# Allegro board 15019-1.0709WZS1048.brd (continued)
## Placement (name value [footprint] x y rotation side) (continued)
R1672  10KR2J-3-GP  [R402H16]  73.52 51.59 270 top
R1673  2K2R2J-2-GP  [R402H16]  84.36 143.51 0 top
R1674  10KR2J-3-GP  [R402H16]  83.35 143.51 0 top
R1675  2K2R2J-2-GP  [R402H16]  56.68 165.74 270 top
R1676  2K2R2J-2-GP  [R402H16]  62.26 156.72 270 top
R1677  47KR2J-2-GP  [R402H16]  52.36 157.86 90 top
R1678  33R2J-2-GP  [R402H16]  56.29 148.84 90 top
R1679  10KR2J-3-GP  [R402H16]  56.8 156.59 270 top
R1683  10KR2J-3-GP  [R402H16]  75.85 49.2 180 top
R1684  10KR2J-3-GP  [R402H16]  70.26 143.38 180 top
R1685  10KR2J-3-GP  [R402H16]  71.28 143.38 0 top
R1686  10R2F-L-GP  [R402H14]  67.98 143.38 0 top
R1687  10KR2J-3-GP  [R402H16]  83.47 138.18 270 top
R1688  10KR2J-3-GP  [R402H16]  83.47 139.19 90 top
R1690  15KR2F-GP  [R402H16]  56.8 160.66 90 top
R1691  15KR2F-GP  [R402H16]  62.26 158.75 90 top
R1696  39D2R2F-L-GP  [R402H16]  94.14 162.69 270 bottom
R1697  0R0402-PAD-2-GP  [0R0402-PAD-1]  86.01 186.56 0 top
R1698  0R0402-PAD-2-GP  [0R0402-PAD-1]  96.17 221.87 0 top
R1699  4K7R2J-2-GP  [R402H16]  115.35 59.56 270 top
R1700  10KR2J-3-GP  [R402H16]  117.25 59.56 90 top
R1701  10KR2J-3-GP  [R402H16]  91.35 222 0 top
R1702  10KR2J-3-GP  [R402H16]  100.11 214.38 90 top
R1703  10KR2J-3-GP  [R402H16]  100.11 215.65 90 top
R1704  1KR2J-1-GP  [R402H16]  100.11 209.3 90 top
R1705  10KR2J-3-GP  [R402H16]  100.11 216.92 90 top
R1707  10KR2J-3-GP  [R402H16]  122.08 204.98 90 top
R1708  0R5J-5-GP  [R805H24]  127.8 205.99 180 bottom
R1709  0R0402-PAD-2-GP  [0R0402-PAD-1]  104.17 217.17 270 top
R1710  0R2J-2-GP  [R402H16]  122.08 216.41 270 top
R1711  0R0402-PAD-2-GP  [0R0402-PAD-1]  104.17 213.11 270 top
R1712  0R0402-PAD-2-GP  [0R0402-PAD-1]  104.17 214.12 270 top
R1713  0R0402-PAD-2-GP  [0R0402-PAD-1]  104.17 211.07 270 top
R1714  0R0402-PAD-2-GP  [0R0402-PAD-1]  104.17 212.09 270 top
R1716  10KR2J-3-GP  [R402H16]  130 217.96 90 top
R1717  0R2J-2-GP  [R402H16]  122.08 221.49 270 top
R1718  0R0402-PAD-2-GP  [0R0402-PAD-1]  122.08 223.52 270 top
R1719  0R0402-PAD-2-GP  [0R0402-PAD-1]  104.17 220.22 270 top
R1720  1KR2J-1-GP  [R402H16]  86.01 190.63 180 top
R1721  1KR2F-3-GP  [R402H16]  161.2 111 90 top
R1724  10KR2J-3-GP  [R402H16]  56.8 168.78 270 top
R1725  10KR2J-3-GP  [R402H16]  105.57 29.59 180 top
R1727  15KR2F-GP  [R402H16]  174.15 125.73 0 top
R1728  10KR2J-3-GP  [R402H16]  173.13 125.73 180 top
R1729  1KR2J-1-GP  [R402H16]  169.71 126.36 90 top
R1730  1KR2J-1-GP  [R402H16]  31.53 35.05 270 top
R1731  10KR2J-3-GP  [R402H16]  31.53 32 270 top
R1732  1KR2J-1-GP  [R402H16]  31.53 29.97 270 top
R1733  10KR2J-3-GP  [R402H16]  31.53 30.99 270 top
R1734  10KR2J-3-GP  [R402H16]  31.53 34.04 270 top
R1735  10R2F-L-GP  [R402H14]  65.44 146.18 270 top
R1736  10KR2J-3-GP  [R402H16]  34.45 135.76 0 top
R1737  10KR2J-3-GP  [R402H16]  35.72 119.89 180 top
R1738  10KR2J-3-GP  [R402H16]  36.99 135.76 0 top
R1739  0R0402-PAD-2-GP  [0R0402-PAD-1]  33.18 119.89 0 top
R1740  0R0402-PAD-2-GP  [0R0402-PAD-1]  35.72 135.76 0 top
R1741  0R0402-PAD-2-GP  [0R0402-PAD-1]  35.34 117.6 90 top
R1743  33R2J-2-GP  [R402H16]  100.11 213.11 90 top
R1744  0R0402-PAD-2-GP  [0R0402-PAD-1]  89.44 213.11 270 top
R1745  0R0402-PAD-2-GP  [0R0402-PAD-1]  89.44 214.38 270 top
R1746  0R0402-PAD-2-GP  [0R0402-PAD-1]  89.44 216.92 270 top
R1747  0R0402-PAD-2-GP  [0R0402-PAD-1]  89.44 218.19 270 top
R1748  0R0402-PAD-2-GP  [0R0402-PAD-1]  89.44 219.46 270 top
R1749  10KR2J-3-GP  [R402H16]  87.66 143.38 0 top
R1751  75R3F-GP  [R603H22]  28.35 18.54 270 bottom
R1752  4K7R2J-2-GP  [R402H16]  30.64 16.13 270 top
R1753  10KR2J-3-GP  [R402H16]  25.18 28.7 90 bottom
R1754  10KR2J-3-GP  [R402H16]  28.99 29.72 270 bottom
R1755  33R2J-2-GP  [R402H16]  32.04 24.26 0 top
R1756  33R2J-2-GP  [R402H16]  27.85 26.67 0 bottom
R1757  10KR2J-3-GP  [R402H16]  36.61 28.57 0 top
R1758  4K7R2J-2-GP  [R402H16]  33.05 26.16 0 top
R1759  10KR2J-3-GP  [R402H16]  29.88 25.15 90 bottom
R1760  10KR2F-2-GP  [R402H16]  26.83 26.67 180 bottom
R1761  0R2J-2-GP  [R402H16]  28.48 17.4 90 bottom
R1762  0R0402-PAD-2-GP  [0R0402-PAD-1]  106.46 8.51 90 top
R1763  0R2J-2-GP  [R402H16]  16.92 159.13 180 bottom
R1764  0R2J-2-GP  [R402H16]  17.94 159.13 0 bottom
R1767  1K5R3-GP  [R603H22]  93.89 7.24 0 top
R1774  0R2J-2-GP  [R402H16]  62.64 148.89 90 top
R1776  47KR2F-GP  [R402H16]  60.23 143.51 270 top
R1777  470KR2F-GP  [R402H16]  91.6 19.56 180 top
R1778  470KR2F-GP  [R402H16]  35.21 141.22 90 top
R1779  1MR2J-1-GP  [R402H16]  91.6 21.46 180 top
R1780  100KR2J-1-GP  [R402H16]  90.58 19.56 180 top
R1781  100KR2J-1-GP  [R402H16]  90.08 21.08 270 top
R1782  4K7R2J-2-GP  [R402H16]  90.08 22.1 90 top
R1783  10KR2J-3-GP  [R402H16]  94.78 23.62 270 top
R1784  0R3J-0-U-GP  [R603H22]  161.73 188.77 90 bottom
R1785  10KR2J-3-GP  [R402H16]  29.62 14.1 0 top
R1808  10KR2F-2-GP  [R402H16]  142.65 72.39 180 top
R1809  10KR2F-2-GP  [R402H16]  141.38 72.39 180 top
R1810  0R2J-2-GP  [R402H16]  142.02 73.91 90 top
R1813  20KR2F-L-GP  [R402H16]  56.8 169.8 270 top
R1816  2KR2F-3-GP  [R402H16]  31.78 8 0 bottom
R1817  15KR2F-GP  [R402H16]  31.4 5.59 90 top
R1819  10KR2J-3-GP  [R402H16]  40.29 9.78 0 top
R1823  10KR2F-2-GP  [R402H16]  131.73 46.86 90 top
R1824  10KR2F-2-GP  [R402H16]  131.68 49.15 90 top
R1825  10KR2J-3-GP  [R402H16]  143.8 64.26 180 top
R1826  10KR2J-3-GP  [R402H16]  162.09 57.66 90 top
R1829  10KR2J-3-GP  [R402H16]  155.1 41.15 0 top
R1830  10KR2F-2-GP  [R402H16]  139.73 45.59 0 top
R1831  4K7R2J-2-GP  [R402H16]  152.69 43.94 0 bottom
R1832  10KR2F-2-GP  [R402H16]  138.84 41.4 90 top
R1833  17K8R2F-GP  [R402H16]  135.92 45.09 0 top
R1834  10KR2F-2-GP  [R402H16]  147.35 56.77 180 bottom
R1835  10KR2F-2-GP  [R402H16]  139.1 48.13 90 bottom
R1837  1KR2J-1-GP  [R402H16]  138.72 50.55 0 top
R1838  17K8R2F-GP  [R402H16]  139.1 47.12 270 top
R1840  10KR2J-3-GP  [R402H16]  144.81 64.26 180 top
R1841  10KR2F-2-GP  [R402H16]  139.1 48.13 270 top
R1842  0R0402-PAD-2-GP  [0R0402-PAD-1]  156.12 47.75 180 bottom
R1843  2K2R2J-2-GP  [R402H16]  146.85 62.48 270 bottom
R1844  4K7R2J-2-GP  [R402H16]  133.38 50.8 180 top
R1845  10KR2J-3-GP  [R402H16]  152.69 56.01 180 bottom
R1846  1K5R3-GP  [R603H22]  60.18 34.74 0 bottom
R1847  100KR3F-L-GP  [R603H22]  66.33 32.38 90 top
R1848  10KR3J-L1-GP  [R603H22]  64.42 44.07 180 top
R1849  10KR2J-3-GP  [R402H16]  53.45 37.16 180 bottom
R1850  56KR3F-GP  [R603H22]  67.85 30.35 0 top
R1851  33R2J-2-GP  [R402H16]  60.18 37.03 180 bottom
R1852  100KR2J-1-GP  [R402H16]  54.47 35.25 180 bottom
R1853  15KR2F-GP  [R402H16]  53.45 35.25 180 bottom
R1857  0R0402-PAD-2-GP  [0R0402-PAD-1]  131.86 57.53 270 top
R1858  0R0402-PAD-2-GP  [0R0402-PAD-1]  36.1 86.49 0 bottom
R1860  4K7R2J-2-GP  [R402H16]  30.26 77.29 180 bottom
R1861  0R2J-2-GP  [R402H16]  72.8 192.41 270 top
R1863  1KR2J-1-GP  [R402H16]  162.09 45.47 90 top
R1864  1KR2J-1-GP  [R402H16]  162.09 51.56 90 top
R1867  2KR2J-1-GP  [R402H16]  80.93 136.14 270 top
R1868  10KR2J-3-GP  [R402H16]  83.47 136.14 270 top
R1869  2KR2J-1-GP  [R402H16]  80.17 138.81 90 top
R1870  10KR2J-3-GP  [R402H16]  78.27 140.08 90 top
R1871  2KR2J-1-GP  [R402H16]  75.47 139.32 90 top
R1872  10KR2J-3-GP  [R402H16]  75.47 140.34 270 top
R1873  2KR2J-1-GP  [R402H16]  54.9 168.78 90 top
R1874  100KR2J-1-GP  [R402H16]  55.15 166.24 180 top
R1875  10KR2J-3-GP  [R402H16]  73.57 139.32 90 top
R1876  10KR2J-3-GP  [R402H16]  80.17 140.84 270 top
R1877  10KR2J-3-GP  [R402H16]  83.47 135.13 270 top
R1878  0R2J-2-GP  [R402H16]  141.94 10.21 270 top
R1901  0R0402-PAD-2-GP  [0R0402-PAD-1]  81.95 186.56 180 top
R1902  0R0402-PAD-2-GP  [0R0402-PAD-1]  78.9 190.63 180 top
R1903  0R0402-PAD-2-GP  [0R0402-PAD-1]  87.03 194.69 180 top
R1904  0R0402-PAD-2-GP  [0R0402-PAD-1]  87.03 190.63 180 top
R1912  0R0402-PAD-2-GP  [0R0402-PAD-1]  95.28 169.8 0 bottom
R1925  0R2J-2-GP  [R402H16]  122.08 222.5 270 top
R1926  10KR2J-3-GP  [R402H16]  86.65 143.38 0 top
R1930  0R2J-2-GP  [R402H16]  24.04 139.57 0 top
R1931  0R2J-2-GP  [R402H16]  104.17 219.2 270 top
R1932  10KR2J-3-GP  [R402H16]  101 222 0 top
R1933  10KR2J-3-GP  [R402H16]  85.63 143.38 0 top
R1934  22R2J-2-GP  [R402H16]  56.68 166.75 90 top
R1935  10KR2J-3-GP  [R402H16]  162.09 54.61 90 bottom
R1953  0R2J-2-GP  [R402H16]  70.77 190.63 180 top
R1954  0R2J-2-GP  [R402H16]  72.3 191.01 270 top
R1980  0R2J-2-GP  [R402H16]  89.7 16.38 0 top
R1981  0R0402-PAD-2-GP  [0R0402-PAD-1]  90.71 16.38 0 top
R1984  0R0402-PAD-2-GP  [0R0402-PAD-1]  46.21 33.4 90 top
R1985  0R0402-PAD-2-GP  [0R0402-PAD-1]  43.59 25.78 0 top
R1986  10KR2J-3-GP  [R402H16]  85.76 211.07 0 bottom
R1987  10KR2J-3-GP  [R402H16]  73.44 208.03 180 bottom
R1988  10KR2J-3-GP  [R402H16]  72.04 211.33 90 bottom
R1989  1KR2F-3-GP  [R402H16]  70.01 211.33 270 bottom
R1993  0R2J-2-GP  [R402H16]  79.92 194.69 180 top
R1994  0R2J-2-GP  [R402H16]  82.96 194.69 180 top
R1995  0R2J-2-GP  [R402H16]  83.98 186.56 180 top
R1998  1KR2J-1-GP  [R402H16]  81.95 194.69 180 top
R1999  0R2J-2-GP  [R402H16]  82.84 196.85 90 top
R2000  1KR2J-1-GP  [R402H16]  85 186.56 180 top
R2001  0R2J-2-GP  [R402H16]  82.96 190.63 180 top
R2002  1KR2J-1-GP  [R402H16]  80.93 194.69 180 top
R2003  196R2F-GP  [R402H16]  60.1 174.24 180 top
R2004  2KR2J-1-GP  [R402H16]  56.8 158.62 270 top
R2008  2KR2J-1-GP  [R402H16]  56.8 155.57 270 top
R2010  10KR2J-3-GP  [R402H16]  56.8 154.56 90 top
R2012  10KR2J-3-GP  [R402H16]  56.8 157.61 90 top
R2013  10KR2J-3-GP  [R402H16]  144.43 39.12 0 top
R2014  10KR2J-3-GP  [R402H16]  145.45 39.12 0 top
R2017  0R0402-PAD-2-GP  [0R0402-PAD-1]  46.01 167 180 top
R2018  100KR2J-1-GP  [R402H16]  47.53 165.61 270 top
R2019  0R2J-2-GP  [R402H16]  49.56 165.61 270 top
R2021  0R2J-2-GP  [R402H16]  52.36 158.88 90 top
R2022  0R3J-0-U-GP  [R603H22]  77.76 194.31 0 top
R2023  0R2J-2-GP  [R402H16]  79.92 197.99 180 top
R2025  0R3J-0-U-GP  [R603H22]  76.49 194.31 180 top
R2026  0R2J-2-GP  [R402H16]  78.9 197.99 180 top
R2028  1KR2F-3-GP  [R402H16]  73.19 142.11 180 top
R2029  0R3J-0-U-GP  [R603H22]  39.28 119.51 0 top
R2030  0R3J-0-U-GP  [R603H22]  38.13 135.38 0 top
R2031  0R3J-0-U-GP  [R603H22]  39.4 135.38 0 top
R2032  0R3J-0-U-GP  [R603H22]  36.99 119.51 0 top
R2053  0R0402-PAD-2-GP  [0R0402-PAD-1]  62.39 135.76 0 top
R2054  0R0402-PAD-2-GP  [0R0402-PAD-1]  154.34 183.64 90 bottom
R2055  10KR2J-3-GP  [R402H16]  143.92 128.65 0 bottom
R2056  10KR2J-3-GP  [R402H16]  146.08 129.16 270 bottom
R2057  1KR2F-3-GP  [R402H16]  143.42 191.9 180 bottom
R2058  1KR2F-3-GP  [R402H16]  144.43 191.9 0 bottom
R2059  1KR2F-3-GP  [R402H16]  150.27 152.91 180 bottom
R2060  1KR2F-3-GP  [R402H16]  150.27 150.88 180 bottom
R2061  10KR2J-3-GP  [R402H16]  144.56 125.98 270 bottom
R2062  10KR2J-3-GP  [R402H16]  146.46 125.98 270 bottom
R2063  2KR2J-1-GP  [R402H16]  56.29 147.83 270 top
R2064  10KR2J-3-GP  [R402H16]  56.29 146.81 90 top
R2065  1KR2F-3-GP  [R402H16]  46.01 169.04 180 top
R2066  1KR2F-3-GP  [R402H16]  52.74 165.61 90 top
R2067  0R2J-2-GP  [R402H16]  69.43 152.43 180 bottom
R2077  10KR2J-3-GP  [R402H16]  28.99 30.73 90 bottom
R2078  0R2J-2-GP  [R402H16]  46.01 164.21 180 top
R2079  0R2J-2-GP  [R402H16]  31.53 74.93 180 top
R2080  0R0402-PAD-2-GP  [0R0402-PAD-1]  55.79 72.14 0 top
R2081  180R3F-GP  [R603H22]  128.28 44.37 90 top
R2082  4D3KR2F-GP  [R402H16]  130.71 41.54 180 top
R2083  2K2R2J-2-GP  [R402H16]  129.82 29.6 180 top
R2084  2K2R2J-2-GP  [R402H16]  130.83 29.6 180 top
R2085  4K7R2F-GP  [R402H16]  131.72 41.54 0 bottom
R2086  4K7R2F-GP  [R402H16]  132.87 29.6 0 top
R2087  4K7R2F-GP  [R402H16]  134.77 41.54 0 top
R2088  4K7R2F-GP  [R402H16]  132.74 41.54 0 top
R2089  4K7R2F-GP  [R402H16]  133.75 41.54 0 bottom
R2090  4K7R2F-GP  [R402H16]  132.74 41.54 0 bottom
R2091  10KR2J-3-GP  [R402H16]  124.24 28.7 0 top
R4230  0R2J-2-GP  [R402H16]  151.42 209.68 270 bottom
R4702  100KR2J-1-GP  [R402H16]  147.23 209.8 90 top
R4706  100KR2J-1-GP  [R402H16]  145.96 199.52 270 top
R4707  1K1R2F-GP  [R402H16]  152.05 215.9 270 bottom
R4708  1K1R2F-GP  [R402H16]  144.05 200.66 270 top
R6701  0R3J-0-U-GP  [R603H22]  75.09 68.35 90 top
R6702  10KR2J-3-GP  [R402H16]  76.11 63.63 180 top
R6703  100KR2J-1-GP  [R402H16]  79.87 63.98 180 top
R6704  100KR2J-1-GP  [R402H16]  77.5 66.6 180 top
R6705  100KR2J-1-GP  [R402H16]  83.4 68 270 top
R6706  0R2J-2-GP  [R402H16]  83.4 66.95 270 top
R79612  75R3F-GP  [R603H22]  65.29 12.27 270 top
R79618  0R2J-2-GP  [R402H16]  80.68 29.08 90 top
R79619  1R5J-2-GP  [R805H24]  38.51 42.93 180 bottom
R79621  10KR2F-2-GP  [R402H16]  44.31 35.48 90 top
R79622  D33R6F-GP  [R1206H26]  49.13 46.58 270 bottom
R79623  300KR2F-GP  [R402H16]  41.33 33.55 270 top
R79625  10KR2F-2-GP  [R402H16]  42.58 31.62 0 top
R79627  300KR2F-GP  [R402H16]  40.42 36.98 270 top
R79628  100KR2F-L1-GP  [R402H16]  35.72 32.03 0 top
R79630  200R5J-GP  [R805H24]  47.81 43.61 180 bottom
R79631  0R1206-PAD-1-GP  [0R1206-PAD-1]  50.45 47.22 270 top
R79633  0R0402-PAD-2-GP  [0R0402-PAD-1]  39.73 32.03 0 top
R79634  0R0402-PAD-2-GP  [0R0402-PAD-1]  38.69 32.03 0 top
R79635  10KR2J-3-GP  [R402H16]  85 135.76 0 top
R79637  10KR2J-3-GP  [R402H16]  151.42 41.15 0 top
R79638  10KR2J-3-GP  [R402H16]  153.07 41.15 0 top
R79639  0R0402-PAD-2-GP  [0R0402-PAD-1]  134.9 29.6 0 top
R79640  0R0402-PAD-2-GP  [0R0402-PAD-1]  135.91 29.6 0 top
R79643  0R5J-5-GP  [R805H24]  59.6 43.69 90 bottom
R79644  0R5J-5-GP  [R805H24]  59.6 45.85 270 top
R79645  0R5J-5-GP  [R805H24]  59.6 39.62 90 bottom
R79646  0R5J-5-GP  [R805H24]  59.6 45.72 90 bottom
R79647  0R2J-2-GP  [R402H16]  35.21 60.33 270 top
R79648  0R2J-2-GP  [R402H16]  35.21 59.31 270 top
R79649  0R2J-2-GP  [R402H16]  157.64 87.5 90 top
R79650  10KR2J-3-GP  [R402H16]  62.26 153.67 270 top
R79651  10KR2J-3-GP  [R402H16]  56.8 167.77 270 top
R79652  10KR2J-3-GP  [R402H16]  77.25 142.11 0 top
R79653  10KR2J-3-GP  [R402H16]  86.14 152.96 270 bottom
R79654  10KR2J-3-GP  [R402H16]  79.66 149.22 90 bottom
R79655  0R3J-0-U-GP  [R603H22]  159.93 142.75 0 top
R79656  0R5J-5-GP  [R805H24]  59.6 41.66 90 bottom
R79657  0R2J-2-GP  [R402H16]  77.93 65.02 90 top
R79658  0R2J-2-GP  [R402H16]  79.15 66.14 90 top
R79659  10KR2J-3-GP  [R402H16]  42.6 113.89 180 top
R79661  1KR2F-3-GP  [R402H16]  41.56 113.92 0 top
R79668  100KR2J-1-GP  [R402H16]  76.36 66.6 0 top
R79669  0R2J-2-GP  [R402H16]  142.91 56.77 270 bottom
R79670  10KR2J-3-GP  [R402H16]  86.01 135.76 0 top
R79671  10KR2J-3-GP  [R402H16]  56.8 153.54 270 top
R79672  10KR2J-3-GP  [R402H16]  81.31 143.51 0 top
R79673  10KR2J-3-GP  [R402H16]  56.8 170.81 270 top
R79674  0R2J-2-GP  [R402H16]  151.42 210.69 270 bottom
R79675  100KR2J-5-GP  [R402H16]  151.42 211.71 270 bottom
R79676  10KR2J-3-GP  [R402H16]  150.27 44.07 270 bottom
R79677  10KR2J-3-GP  [R402H16]  150.27 45.09 270 bottom
R79678  10KR2J-3-GP  [R402H16]  70.9 151 270 bottom
R79679  10KR2J-3-GP  [R402H16]  70.9 153.03 270 bottom
R79680  10KR2J-3-GP  [R402H16]  70.9 152.02 270 bottom
R79681  10KR2J-3-GP  [R402H16]  65.06 138.94 90 top
R79682  33R2J-2-GP  [R402H16]  68.99 139.7 270 top
R79683  33R2J-2-GP  [R402H16]  66.58 139.83 180 top
R79684  33R2J-2-GP  [R402H16]  65.06 137.92 90 top
R79685  33R2J-2-GP  [R402H16]  63.53 138.43 180 top
R79686  0R0402-PAD-2-GP  [0R0402-PAD-1]  148.88 64.26 0 top
R79687  10KR2J-3-GP  [R402H16]  150.91 64.26 180 top
R79688  10KR2J-3-GP  [R402H16]  151.93 64.26 180 top
R79689  10KR2J-3-GP  [R402H16]  162.09 53.59 270 bottom
R79690  10KR2J-3-GP  [R402H16]  162.09 55.63 270 bottom
R79691  0R2J-2-GP  [R402H16]  154.08 41.15 180 top
R79694  10KR2J-3-GP  [R402H16]  86.27 119.51 0 top
R79697  0R2J-2-GP  [R402H16]  107.6 53.09 90 top
R79698  0R2J-2-GP  [R402H16]  115.48 50.42 180 top
R79699  0R2J-2-GP  [R402H16]  116.49 50.42 180 top
R79700  0R2J-2-GP  [R402H16]  114.46 50.42 180 top
R79701  0R2J-2-GP  [R402H16]  110.14 50.8 90 top
R79702  0R2J-2-GP  [R402H16]  110.14 51.82 90 top
R79703  0R2J-2-GP  [R402H16]  110.14 52.83 90 top
R79704  0R2J-2-GP  [R402H16]  108.87 48.64 180 bottom
R79705  10KR2F-2-GP  [R402H16]  103.67 60.58 270 bottom
R79706  10KR2F-2-GP  [R402H16]  101.76 60.58 270 bottom
R79707  0R3J-0-U-GP  [R603H22]  103.79 54.61 0 top
R79708  0R0402-PAD-2-GP  [0R0402-PAD-1]  111.41 63.37 270 top
R79709  0R2J-2-GP  [R402H16]  93.89 50.04 90 bottom
R79710  0R2J-2-GP  [R402H16]  95.16 48.9 270 bottom
R79711  0R2J-2-GP  [R402H16]  109.51 54.23 90 bottom
R79712  0R2J-2-GP  [R402H16]  94.39 57.66 270 bottom
R79713  0R2J-2-GP  [R402H16]  109.63 55.5 90 bottom
R79714  10KR2J-3-GP  [R402H16]  84.87 145.54 180 bottom
R79720  100KR2F-L1-GP  [R402H16]  108.11 60.58 270 bottom
R79721  33KR2J-3-GP  [R402H16]  108.11 61.72 90 bottom
R79722  100KR2F-L1-GP  [R402H16]  109.89 58.04 180 top
R79723  10KR2F-2-GP  [R402H16]  109.89 56.13 180 top
R79724  0R2J-2-GP  [R402H16]  147.86 200.66 90 top
R79725  0R2J-2-GP  [R402H16]  145.96 200.66 90 top
R79726  10KR5F-2-GP  [R805H24]  33.05 20.57 90 bottom
R80201  4K7R2J-2-GP  [R402H16]  25.05 10.29 0 bottom
R80202  4K7R2J-2-GP  [R402H16]  26.07 10.29 0 bottom
R80206  0R2J-2-GP  [R402H16]  147.73 44.07 0 bottom
R80207  0R2J-2-GP  [R402H16]  150.27 41.15 180 top
R80208  0R2J-2-GP  [R402H16]  147.73 39.5 90 top
R80209  0R2J-2-GP  [R402H16]  147.23 41.02 180 top
R80210  0R2J-2-GP  [R402H16]  146.21 41.02 180 top
R80211  0R2J-2-GP  [R402H16]  145.19 41.02 180 top
R80212  10KR2J-3-GP  [R402H16]  102.27 56.64 0 top
R80213  0R2J-2-GP  [R402H16]  106.59 41.15 180 top
R80215  15KR2F-GP  [R402H16]  139.48 43.43 90 top
R80216  10KR2F-2-GP  [R402H16]  141.64 43.81 0 bottom
R80217  10KR2J-3-GP  [R402H16]  157.77 43.56 180 bottom
R80218  10KR2J-3-GP  [R402H16]  158.28 41.78 270 bottom
R80219  0R2J-2-GP  [R402H16]  140.75 64.39 180 bottom
R80220  0R2J-2-GP  [R402H16]  139.73 64.39 180 bottom
R80221  10KR2J-3-GP  [R402H16]  162.21 48.51 90 top
R80222  10KR2J-3-GP  [R402H16]  162.21 49.53 90 top
R80223  0R2J-2-GP  [R402H16]  162.09 46.48 270 top
R80224  0R2J-2-GP  [R402H16]  146.85 61.47 270 bottom
R80225  0R0402-PAD-2-GP  [0R0402-PAD-1]  72.3 189.99 270 top
R80226  0R2J-2-GP  [R402H16]  157.89 49.78 180 bottom
R80227  0R2J-2-GP  [R402H16]  20.73 164.47 180 top
R80228  8K2R2J-3-GP  [R402H16]  88.93 55.24 270 bottom
R80229  39K2R2F-L-GP  [R402H16]  87.28 54.74 180 bottom
R80230  10KR2J-3-GP  [R402H16]  92.62 51.56 0 bottom
R80231  0R2J-2-GP  [R402H16]  155.23 64.14 180 top
R80232  0R2J-2-GP  [R402H16]  164.24 56.13 0 top
R80233  10KR2J-3-GP  [R402H16]  41.56 116.97 270 bottom
R90001  0R3J-0-U-GP  [R603H22]  116.64 105.13 0 top
R90002  0R3J-0-U-GP  [R603H22]  115.73 99.95 0 bottom
R90004  0R2J-2-GP  [R402H16]  94.9 103.5 90 top
R90005  0R2J-2-GP  [R402H16]  96.05 100.97 90 top
R90006  10R2J-2-GP  [R402H14]  107.22 98.04 270 bottom
R90007  10R2J-2-GP  [R402H14]  107.35 93.09 180 top
R90008  0R3J-0-U-GP  [R603H22]  118.19 105.08 180 top
R90009  0R3J-0-U-GP  [R603H22]  116.64 107.9 0 top
R90010  0R3J-0-U-GP  [R603H22]  117.38 100.08 180 bottom
R90011  0R3J-0-U-GP  [R603H22]  120.05 100.08 180 bottom
R90012  10KR2J-3-GP  [R402H16]  107.22 99.19 90 bottom
R90013  10KR2J-3-GP  [R402H16]  94.52 101.47 180 top
R90014  10KR2J-3-GP  [R402H16]  94.52 105.79 0 top
R90015  10KR2J-3-GP  [R402H16]  93.38 107.44 180 top
R90016  10KR2J-3-GP  [R402H16]  93.38 104.9 180 top
R90017  10KR2J-3-GP  [R402H16]  94.52 99.44 0 top
R90018  10KR2J-3-GP  [R402H16]  93.25 98.55 180 top
R90019  10KR2J-3-GP  [R402H16]  95.66 96.39 0 top
R90020  10KR2J-3-GP  [R402H16]  93.38 102.36 0 top
R90021  10KR2J-3-GP  [R402H16]  95.66 98.3 180 top
R90030  25K5R2F-GP  [R402H16]  59.09 87.73 90 top
R90031  100KR2F-L1-GP  [R402H16]  61.68 87.27 0 top
R90032  10KR2J-3-GP  [R402H16]  66.78 92.79 90 top
R90033  22R2J-2-GP  [R402H16]  80.93 105.66 270 top
R90034  22R2J-2-GP  [R402H16]  80.55 106.81 270 top
R90035  22R2J-2-GP  [R402H16]  80.93 104.52 270 top
R90036  22R2J-2-GP  [R402H16]  80.93 99.95 270 top
R90037  22R2J-2-GP  [R402H16]  80.93 103.38 270 top
R90038  22R2J-2-GP  [R402H16]  80.93 101.09 270 top
R90039  4K7R2J-2-GP  [R402H16]  80.93 107.95 270 top
R90040  10KR2F-2-GP  [R402H16]  81.19 104.9 180 bottom
R90041  10KR2F-2-GP  [R402H16]  77.5 96.01 180 top
R90042  22R2J-2-GP  [R402H16]  80.93 98.81 270 top
R90043  22R2J-2-GP  [R402H16]  80.93 96.52 270 top
R90044  22R2J-2-GP  [R402H16]  80.93 102.23 270 top
R90045  22R2J-2-GP  [R402H16]  80.3 97.66 270 top
R90046  100KR2J-1-GP  [R402H16]  68.11 95.12 180 top
R90047  10KR2J-3-GP  [R402H16]  82.33 105.92 0 bottom
R90048  10KR2J-3-GP  [R402H16]  81.19 106.81 0 bottom
R90050  470KR2F-GP  [R402H16]  73.95 110.36 180 top
R90051  10KR2J-3-GP  [R402H16]  71.66 110.36 0 top
R90052  10KR2J-3-GP  [R402H16]  67.09 110.36 180 top
R90053  10KR2J-3-GP  [R402H16]  68.23 110.36 180 top
R90054  10KR2J-3-GP  [R402H16]  70.52 110.36 180 top
R90055  10KR2J-3-GP  [R402H16]  65.95 110.36 0 top
R90056  10KR2J-3-GP  [R402H16]  69.38 110.36 0 top
R90057  1MR3F-GP  [R603H22]  66.12 101.8 0 top
R90064  0R2J-2-GP  [R402H16]  66.07 95.12 0 top
R90065  0R2J-2-GP  [R402H16]  64.93 95.12 180 top
R90066  1KR2F-3-GP  [R402H16]  113.06 91.19 180 top
R90067  47KR2J-2-GP  [R402H16]  113.06 93.09 0 top
R90068  10KR2J-3-GP  [R402H16]  162.09 57.66 270 bottom
R90069  0R3J-0-U-GP  [R603H22]  81.03 88.67 180 top
R90070  0R3J-0-U-GP  [R603H22]  79.81 88.67 180 top
R90071  0R3J-0-U-GP  [R603H22]  119.29 102.36 270 bottom
R90072  0R3J-0-U-GP  [R603H22]  121.32 101.6 0 bottom
R90073  10KR2J-3-GP  [R402H16]  83.98 109.22 180 top
R90074  10KR2J-3-GP  [R402H16]  85.12 109.22 0 top
R90075  10KR2J-3-GP  [R402H16]  72.8 110.36 0 top
R90076  680R2F-GP  [R402H16]  67.29 103.4 180 top
RJ1  RJ45-8P-199-GP  [23-01120-2A03-A]  76.92 21.04 180 top
RN7  SRN10KJ-6-GP  [ARES8-CN24-MUH20]  154.59 56.01 0 bottom
RN8  SRN10KJ-5-GP  [ARES2H18]  147.35 64.77 180 top
RN9  SRN10KJ-5-GP  [ARES2H18]  142.27 64.77 180 top
RN10  SRN10KJ-6-GP  [ARES8-CN24-MUH20]  146.46 53.47 90 bottom
RN12  SRN1KJ-8-GP  [SMD-ARES8-1H26]  96.43 209.17 0 bottom
RN13  SRN33J-7-GP-U  [ARES8-CN24-UH20]  153.45 52.7 180 bottom
RN4301  SRN33J-7-GP-U  [ARES8-CN24-UH20]  35.21 65.15 270 bottom
RT1  NTC-10K-19-GP-U  [NTC-402H22-U]  100.11 172.85 180 top
RT2  NTC-10K-19-GP-U  [NTC-402H22-U]  85.76 85.52 0 top
RT3  NTC-10K-19-GP-U  [NTC-402H22-U]  18.19 190.5 180 top
RV1  P4500SCLHLRP-GP  [TVS5436-1121H105]  65.06 18.8 0 top
SATAP1  CLX-CON5-18-GP-U  [CI2505P1H00-LF-U]  12 195 270 top
SPI1  MX25L6406EM2I-12G-GP  [SOIC8-1H86]  35.09 127.25 180 top
SPK1  JWT-CON6-20-GP  [A1501WV0-6PS-5E]  147.84 14.27 180 top
SPR1  SPRING-62-GP  [SPR10637H367]  165.4 172.7 270 top
SRCON1  SKT-SPI8P-GP-U1  [SKT-SOIC8-092117H235]  35.09 127.25 0 top
SSUSB1  SKT-USB11-112-GP-U  [SKT-USB11-138165-1]  176.12 116.84 90 top
SSUSB2  SKT-USB11-112-GP-U  [SKT-USB11-138165-1]  176.12 95.34 90 top
TC1  ST330U2D5VDM-9GP  [CT7343H75]  133.76 204.09 270 bottom
TC7  E100U16VM-47-GP  [ECAP-100D6D3H237]  107.48 24.51 270 top
TC8  E100U16VM-47-GP  [ECAP-100D6D3H237]  166.91 101.6 0 top
TOUCH1  ENT-CON5-GP  [3703K-Q05N-11L]  24.7 8.5 270 top
TP6  -  [TPAD28]  74.33 175.39 180 bottom
TP8  -  [TPAD28]  73.44 150.37 180 bottom
TP9  -  [TPAD28]  74.91 162.71 180 bottom
TP24  -  [TPAD28]  157.77 35.81 180 top
TP25  -  [TPAD28]  155.23 42.8 270 top
TP26  -  [TPAD28]  153.96 42.8 270 top
TP28  -  [TPAD28]  140.88 46.23 270 top
TP37  -  [TPAD28]  88.81 156.21 180 bottom
TP38  -  [TPAD28]  121.32 215.26 0 top
TP39  -  [TPAD28]  122.59 215.26 0 top
TP62  -  [TPAD28]  107.22 208.03 0 top
TP63  -  [TPAD28]  122.59 207.65 0 top
TP64  -  [TPAD28]  121.32 207.65 0 top
TP65  -  [TPAD28]  121.32 212.72 0 top
TP66  -  [TPAD28]  122.59 212.72 0 top
TP67  -  [TPAD28]  121.32 214 0 top
TP68  -  [TPAD28]  122.59 211.46 0 top
TP69  -  [TPAD28]  121.32 211.46 0 top
TP70  -  [TPAD28]  122.59 210.19 0 top
TP71  -  [TPAD28]  121.32 210.19 0 top
TP72  -  [TPAD28]  122.59 208.91 0 top
TP73  -  [TPAD28]  121.32 208.91 0 top
TP74  -  [TPAD28]  105.95 208.03 0 top
TP75  -  [TPAD28]  104.68 208.03 0 top
TP76  -  [TPAD28]  107.22 209.93 0 top
TP77  -  [TPAD28]  105.95 209.93 0 top
TP78  -  [TPAD28]  104.68 209.93 0 top
TP79  -  [TPAD28]  105.95 220.47 0 top
TP80  -  [TPAD28]  107.22 220.47 0 top
TP81  -  [TPAD28]  105.95 222.12 0 top
TP82  -  [TPAD28]  107.22 222.12 0 top
TP83  -  [TPAD28]  105.95 223.77 0 top
TP84  -  [TPAD28]  107.22 223.77 0 top
TP174  -  [TPAD28]  73.06 175.26 180 bottom
TP175  -  [TPAD28]  90.2 156.21 180 bottom
TP176  -  [TPAD28]  89.82 171.83 180 bottom
TP177  -  [TPAD28]  89.36 173.33 180 bottom
TP178  -  [TPAD28]  90.08 154.94 180 bottom
TP179  -  [TPAD28]  76.94 165.28 180 bottom
TP180  -  [TPAD28]  75.55 166.42 180 bottom
TP181  -  [TPAD28]  75.85 188.34 0 top
TP182  -  [TPAD28]  77 188.98 0 top
TP183  -  [TPAD28]  78.01 188.21 0 top
TP184  -  [TPAD28]  90.71 173.61 180 bottom
TP186  -  [TPAD28]  77.12 143.76 0 top
TP187  -  [TPAD28]  79.51 150.47 180 bottom
TP188  -  [TPAD28]  74.33 48.01 90 bottom
TP189  -  [TPAD28]  75.85 50.85 0 top
TP190  -  [TPAD28]  68.87 141.1 0 top
TP192  -  [TPAD28]  82.25 178.92 180 bottom
TP193  -  [TPAD28]  79.79 180.85 180 bottom
TP194  -  [TPAD28]  78.21 179.55 180 bottom
TP195  -  [TPAD28]  81.41 180.57 180 bottom
TP196  -  [TPAD28]  122.59 214 0 top
TP198  -  [TPAD28]  77 158.12 180 bottom
TP199  -  [TPAD28]  76.11 155.19 180 bottom
TP208  -  [TPAD28]  123.73 222.5 0 top
TP210  -  [TPAD28]  95.16 174.12 180 bottom
TP211  -  [TPAD28]  96.76 173.69 180 bottom
TP212  -  [TPAD28]  100.62 155.83 0 top
TP213  -  [TPAD28]  89.82 174.88 180 bottom
TP214  -  [TPAD28]  76.61 163.91 180 bottom
TP215  -  [TPAD28]  140.88 53.09 0 top
TP4124  -  [TPAD28]  95.54 56.52 180 bottom
TP4125  -  [TPAD28]  94.27 56.52 180 bottom
TP4126  -  [TPAD28]  93 53.98 180 bottom
TP4127  -  [TPAD28]  94.27 53.98 180 bottom
TP4128  -  [TPAD28]  95.54 53.98 180 bottom
TP4129  -  [TPAD28]  94.27 55.24 180 bottom
TP4130  -  [TPAD28]  95.54 55.24 180 bottom
TP4142  -  [TPAD28]  65.18 179.32 180 bottom
TP4143  -  [TPAD28]  62.39 179.32 180 bottom
TP4144  -  [TPAD28]  65.18 181.1 180 bottom
TP4145  -  [TPAD28]  62.39 181.1 180 bottom
TP4146  -  [TPAD28]  65.18 182.75 180 bottom
TP4147  -  [TPAD28]  62.39 182.75 180 bottom
TP4148  -  [TPAD28]  62.39 184.66 180 bottom
TP4149  -  [TPAD28]  65.06 184.53 180 bottom
TP5001  -  [TPAD28]  69.63 169.42 180 bottom
TP5002  -  [TPAD28]  69.5 170.69 180 bottom
TP5003  -  [TPAD28]  81.44 147.07 180 bottom
TP5004  -  [TPAD28]  79.15 141.73 180 bottom
TP5005  -  [TPAD28]  70.9 171.32 180 bottom
TP5006  -  [TPAD28]  70.9 170.05 180 bottom
TP5007  -  [TPAD28]  68.49 171.83 180 bottom
TP5008  -  [TPAD28]  68.49 173.1 180 bottom
TP5009  -  [TPAD28]  69.76 174.62 180 bottom
TP5010  -  [TPAD28]  69.76 173.35 180 bottom
TP5011  -  [TPAD28]  69.76 176.02 180 bottom
TP5012  -  [TPAD28]  70.9 176.66 180 bottom
TP5013  -  [TPAD28]  107.58 96.9 0 bottom
TP5014  -  [TPAD28]  104.17 102.23 0 bottom
TP5015  -  [TPAD28]  104.17 103.5 0 bottom
TP5016  -  [TPAD28]  105.82 104.78 0 bottom
TP5017  -  [TPAD28]  108.26 104.72 0 bottom
TR1  FILTER-4P-137-GP-U  [L125100-4P-4H28]  153.07 197.61 0 top
TR3  FILTER-4P-137-GP-U  [L125100-4P-4H28]  164.24 108.71 0 top
TR4  FILTER-4P-137-GP-U  [L125100-4P-4H28]  164.24 106.55 0 top
TR9  MCM1012B900FBP-GP-U  [L125100-4P-1H37]  31.78 13.34 90 top
TR10  FILTER-4P-137-GP-U  [L125100-4P-4H28]  95.11 33.91 270 top
TR12  MCM1012B900FBP-GP-U  [L125100-4P-1H37]  106.21 206.25 180 top
TR14  FILTER-4P-137-GP-U  [L125100-4P-4H28]  92.82 33.91 270 top
TR16  FILTER-4P-120-GP  [L125100-4P-1H28]  126.78 32.27 0 top
TR17  FILTER-4P-120-GP  [L125100-4P-1H28]  126.78 34.43 0 top
TR18  FILTER-4P-120-GP  [L125100-4P-1H28]  126.78 36.71 0 top
TR19  FILTER-4P-120-GP  [L125100-4P-1H28]  126.78 38.87 0 top
U1  AO6402A-GP  [SOT-6-1H50]  32.16 109.17 0 bottom
U2  AO4468L-GP  [SOIC8H69]  48.17 141.1 0 top
U3  AZ1045-04F-R7G-GP  [DFN10G2510H26]  168.94 116.84 270 top
U5  AZ1045-04F-R7G-GP  [DFN10G2510H26]  168.94 95.38 270 top
U6  ALC3661-CG-GP  [QFN48J6-G465H40]  162.59 78.23 0 top
U7  MX25L1006EMI-10G-GP  [SOIC8H69]  125.46 48.51 90 top
U10  AZC099-04S-1-GP  [SOT-6H58]  47.2 11.94 270 top
U11  AZC099-04S-1-GP  [SOT-6H58]  47.2 11.94 270 bottom
U12  AZC099-04S-1-GP  [SOT-6H58]  77.25 29.08 270 top
U16  RTL8111G-CGT-1-GP-U2  [QFN32J4-G2D85H36]  37.88 14.86 270 top
U21  TPA3131D2RHBR-GP-U  [QFN32-G3D55H40]  155.35 30.61 270 top
U25  M24C64-WMN6TP-2-GP  [SOIC8H69]  38.01 81.79 180 bottom
U26  RTD2136S-CG-GP  [QFN48J6-G4D55H40]  37.78 94.5 270 bottom
U31  AZ1045-04F-R7G-GP  [DFN10G2510H26]  123.48 37.36 90 top
U52  TPS22966DPUR-GP  [SON14J3020-G2610H34]  145.63 7.04 90 top
U54  TPS22966DPUR-GP  [SON14J3020-G2610H34]  90.33 11.81 0 top
U55  BQ24727RGRR-1-GP  [QFN20G3D5-G2D15H40]  60.74 56.26 180 bottom
U105  AO6402A-GP  [SOT-6-1H50]  43.47 131.19 270 top
U109  IT8739E-GP  [LQFP128H63]  150.66 52.58 270 top
U110  AO4407AL-GP  [SOIC8H69]  66.33 38.99 0 top
U116  AZ1045-04F-R7G-GP  [DFN10G2510H26]  123.48 33.78 270 top
U117  AZ1045-04F-R7G-GP  [DFN10G2510H26]  123.48 40.89 270 top
U118  PS8407ATQFN40GTR2-A1-GP  [QFN40J5-G3D65H32]  132.74 35.57 270 top
U119  AZ1117CR-ADJTRG1-GP-U  [SOT-89-4541-3PH63]  131.45 46.74 90 bottom
U120  OZ554ALN-B-0-TR-GP  [QFN20-G2D1H32]  37.37 36.58 90 bottom
U178  TS3702IDT-GP  [SOIC8H69]  147.35 204.85 0 top
U902  OZ788WR2IBN-A-0-TR-GP  [CSP97G60-1H41]  73.06 102.36 0 top
U903  KLMBG4GEND-B031-GP  [BGA153G115130-1H40]  107.02 101.96 90 top
U4101  NPCE948LA0DX-GP  [LQFP64H63]  102.27 54.48 0 bottom
U6701  KXCNL-1010-GP  [LGA16G3-1H40]  79.03 69.9 0 top
U9001  RT9025-25ZSP-1-GP  [SOIC8-G2D3H70]  66.25 88.34 90 top
U9003  MX25L5121EMC-20G-GP  [SOIC8H69]  72.55 94.23 90 top
UHS1  AUDIO-JK500-GP  [2SJ3082-038111F]  176.5 75.29 90 top
UR5  330R2F-GP  [R402H16]  80.68 28.07 90 top
UR6  330R2F-GP  [R402H16]  73.69 30.1 270 top
UR7  330R2F-GP  [R402H16]  73.69 29.08 270 top
USB3  SKT-USB6-174-GP  [SKT-USB6-135063]  98.35 37.03 90 top
USB4  SKT-USB6-174-GP  [SKT-USB6-135063]  98.35 14.03 90 top
WEBCM1  JWT-CON8-4-GP  [A1251WR0-8PS-5E]  160.12 201.1 180 top
X1  XTAL-48MHZ-27-GP-U  [OSC-3225-4P-4H36]  62.52 172.85 90 top
X2  XTAL-32D768KHZ-67-GP  [SMD49-6914-0403H56]  59.72 150.88 180 top
X4  XTAL-25MHZ-181-GP  [OSC-3225-4P-4H36]  36.74 6.86 0 top
X54  XTAL-30MHZ-22-GP  [SMD-OSC19H20]  63.63 102.74 270 top
XF1  XFORM-12P-48-GP  [XFORM12A127097H91]  56.29 11.94 90 top
XF2  XFORM-12P-48-GP  [XFORM12A127097H91]  56.29 11.94 270 bottom

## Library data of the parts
AFTP1 = AFTE14P-75: tolerance: ZZ.AFT14.101
BAT2 = 50290-0100N-001: tolerance: 20.F2196.010
BT1 = AAA-BAT-034-K01: tolerance: 62.70010.031
BTRST1 PSWD1 = A2541WV0-1EX2PA-6T: tolerance: 21.60909.102
C1 C6 C41 C42 C44-C46 C60 C84 C91 C101 C103 C111 C113 C122 C131 C145 C147 C197 C204 C211 C213 C231 C238 C284 C289 C290 C293 C295 C297-C305 C316 C337 C353 C392 C483 C495 C549 C550 C558 C570 C572 C574 C582-C585 C587 C595 C714 C721 C869 C1609 C1617 C1701 C1723 C1731 C1732 C1737 C1742 C1746 C1753 C1754 C1757 C1758 C1769 C1805 C1806 C1808-C1818 C1820 C1826 C1832 C1834 C1877 C1926 C1961 C1966-C1970 C1977 C1979 C1982 C3366 C3368-C3375 C3377-C3379 C3382 C3383 C3453 C3454 C6701 C6702 C6721 C9010 C9011 C9013 C9016 C9018 C9019 C9021 C9022 C9031 C9032 C9038 C9040 PC96 PC4607 PC4619 PC4802 PC5213 = C402H22: tolerance: 78.10421.2FLDL
C2 C3 C72 C109 C127 C129 C474 C478 C485 C1674 C1677 C1695 C1702 C1704-C1707 C1714 C1715 C1743 C1744 C6714 C6715 C9007 C9009 C9012 C9014 C9015 C9017 C9020 C9023 C9039 = C603H36: tolerance: 78.10610.5BLDL
C4 C20 = C603H36: tolerance: 78.47523.5BLDL
C5 = C603H36: tolerance: 78.47422.5BLDL
C7 C9 C11 C100 C170 C591 C593 C863 C864 C866 C871 C1616 C1739 C1798 C1827 C1957 C9037 = C402H22: tolerance: 78.10523.5FL
C8 C15 C65 C1608 C1727 C1836 C1837 C1928 C1929 C1959 C1980 C1981 PC4601 PC4605 PC4606 PC4618 PC4622 PC4706 PC4712 PC4804 PC4807 PC5003 PC5235 PC5405 PC5413 PC5414 PC5418 = C402H22: tolerance: 78.10224.2FLDL
C10 C134 C157 C159 C160 C194 C203 C267 C268 C1780 C6722 PC5244 = C402H22: tolerance: 78.10134.1FLDL
C14 C141 C142 C149 C151 C1764 C1870 C3376 C3380 C3381 C3452 C3457 C3458 C9026-C9029 PC4609 PC4614 PC4616 PC4901 PC4905 PC5232 = C402H22: tolerance: 78.10324.2FLDL
C32 = C603H36: tolerance: 78.10492.4BLLL
C33 = C402H22: tolerance: 78.27034.1FLLL
C35 = C603H36: tolerance: 78.33135.1BL
C36-C39 = C1206H75: tolerance: 078.10525.022D
C40 = C1206H71: tolerance: 78.10525.22LLL
C43 C3456 = C402H22: tolerance: 78.10422.5FLLL
C48 C543 C551 C3459 C3460 PC4401 PC4406 PC4407 PC5240 PC5241 = C805H58: tolerance: 78.10622.51LDL
C50 C52 = C402H22: tolerance: 78.5R674.1FLDL
C55 C138 C139 C1724 C1725 C1971-C1973 C9034 C9035 PC4914 = C603H36: tolerance: 78.47520.5BLDL
C57 C9024 C9025 PC4301 PC4305 PC4612 PC4627 PC5416 = C402H22: tolerance: 78.10034.1FLDL
C58 = C402H22: tolerance: 78.8R064.1FLDL
C61 C77 C1735 = C402H22: tolerance: 78.10322.2FL
C66 C121 C132 C1733 C1734 C9008 = C402H22: tolerance: 78.10134.1FL
C67 = C402H22: tolerance: 78.10321.2FL
C73 C202 C209 C1803 C1804 = C603H36: tolerance: 78.47520.5BL
C74 C87 C88 C106 C516 C580 C1729 C1730 C1747 C1760 C1930 C1975 C1976 = C402H22: tolerance: 78.10421.2FL
C75 C140 C579 C1615 C1745 C1802 PC4608 = C603H36: tolerance: 78.22523.5BLDL
C76 C1738 = C402H22: tolerance: 78.15134.1FLDL
C78 C99 C150 C395 C562 C1491 C1638 C1639 C1698 C1699 C1728 C1736 C1821 C1825 C1829 C1830 C1960 C4101 C4102 C9006 C9036 C9041 PC1 PC140 PC4803 PC4906 PC4909 PC4910 PC5009 PC5018 PC5204 PC5233 = C402H22: tolerance: 78.10523.5FLDL
C94 C1768 C1807 = C603H36: tolerance: 78.10422.2BL
C95 C105 C227 C315 C1748 C1752 C1833 C1835 C1925 C1927 = C805H54: tolerance: 78.10623.51L
C104 C112 C144 C146 C154 C155 C283 C292 C296 C450 C592 C1770 C1771 C3367 PC5001 PC5011 PC5016 PC5247 PC5248 = C805H50: tolerance: 78.10623.51LDL
C110 C192 C193 C208 C260 C1801 PC4602 PC5420 = C603H36: tolerance: 78.10522.5BLDL
C126 PC126 = C402H22: tolerance: 78.22034.1FL
C130 = C402H22: tolerance: 78.10422.5FL
C190 PC49 PC4912 PC5012 PC5243 PC5246 PC5427-PC5429 = C603H36: tolerance: 78.10521.2BLDL
C198-C200 C210 = C603H36: tolerance: 78.27324.2BLDL
C222 C239 C243 C263 = C603H36: tolerance: 78.10324.2BL
C223 C224 C228 C229 C865 PC4704 PC4710 PC5411 = C603H36: tolerance: 78.22422.2BLDL
C225 C235 C247 C255 = C603H36: tolerance: 78.68421.5BL
C226 C236 C248 C256 = C603H36: tolerance: 78.10234.1BLDL
C249 C857 C862 = C603H36: tolerance: 78.10424.2BL
C258 C545 C552 C597 PC51 PC4302 PC4402-PC4404 PC4703 PC4709 PC4713 PC4806 PC4903 PC4907 PC4908 PC5010 PC5019 PC5234 PC5236 PC5242 PC5403 = C603H35: tolerance: 78.10424.2BLDL
C262 = C402H22: tolerance: 78.10324.2FL
C291 C565 C1824 = C805H54: tolerance: 78.22610.51LDL
C326 C330 C356 C1697 C1871 C1876 C1962 C1978 = C402H22: tolerance: 78.18134.1FLDL
C493 C509 C1953 C1956 C6703 = C603H38: tolerance: 78.10610.5BL
C521 C1796 C1797 = C603H36: tolerance: 78.10521.5BL
C524 PC4303 PC4611 PC4626 PC5417 = C402H22: tolerance: 78.22224.2FLDL
C525 C542 C1823 = C402H22: tolerance: 78.10491.4FL
C531 C589 C1756 = C402H22: tolerance: 78.10224.2FL
C548 = C402H22: tolerance: 78.22510.5FL
C872 C1755 = C402H22: tolerance: 78.68321.2FLDL
C1644-C1656 C1673 C1678-C1688 C1934-C1936 C1938 C1947-C1951 PC5205 PC5210-PC5212 = C603H40: tolerance: 78.22610.5BLDL
C1657-C1672 C1689-C1694 C1696 C1703 C1708 C1716 C1741 C1828 C1872-C1875 C1939-C1946 C1952 C1954 C1963-C1965 C1974 C6712 = C402H22: tolerance: 078.22423.05FD
C1700 C1831 = C402H22: tolerance: 78.10520.5FLDL
C1721 C1722 = C402H22: tolerance: 78.15124.2FL
C1726 C1958 PC34 PC48 PC5245 = C402H22: tolerance: 78.10423.2FL
C1773 C1774 = C402H22: tolerance: 78.10034.1FL
C1799 = C402H22: tolerance: 78.15034.1FLDL
C1800 = C402H22: tolerance: 78.12034.1FLDL
C1937 = C402H22: tolerance: 78.18134.1FL
C3131 = C1808H87: tolerance: 078.1013N.014D
C3455 PC4405 PC5217 PC5238 = C402H22: tolerance: 78.10422.5FLDL
C6718-C6720 = C603H36: tolerance: 78.10422.2BLDL
C6724 PC5423 PC5424 = C402H22: tolerance: 78.10322.2FLDL
C6725 = C402H20: tolerance: 78.10423.5FL
C6726-C6729 = C402H22: tolerance: 78.4R774.1FLDL
CN1 = 14300002: tolerance: 21.60257.102
CONVT1 = CI1410M1HRL-NH: tolerance: 20.F2266.010
CPU1 = BGA968M2937H74: tolerance: 071.FUSIN.000U
D1 D31 = SOD323AKH38: tolerance: 83.00355.D1F
D4 D24 = SOT-6H44: tolerance: 75.04223.07C
D16 = DO214AAAK-1121H97: tolerance: 83.P6SMB.KAG
D19 = SOT23-2D4-312H48: tolerance: 75.00099.F7D
D20 = SOT23-2D4-312H44: tolerance: 75.00054.I7D
D21 = SOD523AKH28: tolerance: 83.02015.0AF
D23 = SOT23-2D4-312H44: tolerance: 75.00054.T7D
D32 = D4724AKH44: tolerance: 83.3R010.C8M
D33 = SOD80CH36: tolerance: 83.R5003.C8F
DCIN1 = 2DC3115-000111F: tolerance: 022.10015.0311
DCIN2 = 88314-077N: tolerance: 20.F1498.007
DIMM1 = AS0A621-J4R6-7H-U: tolerance: 62.10024.S21
DIMM2 = AS0A626-J8R6-7H: tolerance: 62.10024.G01
F1 F3 F6 F13 F15 = POLYSW-2114H30: tolerance: 069.50001.0031
F2 F5 F12 F14 = POLYSW-2114H30: tolerance: 069.50003.0001
F16 = FUSE-1608H22: tolerance: 69.43001.441
FANC3 = HF1804H: tolerance: 021.D0086.0104
G5 PG4701-PG4704 PG5401 PG5402 = CON2C-U: tolerance: ZZ.CON2C.XXX
H1-H5 = HOLE237R158: tolerance: ZZ.0HOLE.011
H6 H9 = GEN8D5X8R5X4D5-8-F-A: tolerance: ZZ.00PAD.BV1
H7 = GEN315R138-8-F-A-1: tolerance: ZZ.00PAD.BU1
H10 = GEN315R178-8-F-A-1: tolerance: ZZ.00PAD.BR1
H11 = GEN315R138-8-F-A-2-S: tolerance: ZZ.00PAD.HK1
HDD1 = 15-02070-5A61-A: tolerance: 020.80244.0007
HDMI1 = SKT-HDMI22-150077: tolerance: 062.10012.0121
HDMI2 = LVDFH-02004-TP00: tolerance: 20.F2139.020
HDT1 = ASP-137098-05: tolerance: 20.F1722.020
HS6 = STF256R109H99: tolerance: 34.3NH01.001
L1 = L20125H42: tolerance: 68.00216.121
L2 = L3030-2709H41: tolerance: 68.2R21F.10E
L4 L5 L56 L57 L4102 L4103 = L125100-4P-1H36: tolerance: 68.12105.201
L10 = L603H38: tolerance: 68.00335.141
L15 = L402H22: tolerance: 68.00084.541
L16 L17 L19 = L603H38: tolerance: 68.00230.231
L20 L21 L54 L62 = L402H24: tolerance: 68.00213.031
L31-L34 = L20125H42: tolerance: 68.00216.111
L46 PR4814 PR4815 PR4927 PR4929-PR4933 PR5018-PR5021 PR5032 PR5290 R101 R183 R185 = 0R0805-PAD: tolerance: ZZ.R0805.ZZZ
L55 = L1608-UH38: tolerance: 68.00217.171
L60 = L603H38: tolerance: 68.00335.081
L61 = L8080-6522-1H166: tolerance: 068.33010.1041
L4101 = L402H22: tolerance: 68.00084.I21
LED2 LED3 = LED1608AKH30: tolerance: 83.01608.Q70
LOUT1 = JAC331-0140A8B-9H: tolerance: 22.10277.2M1
LPC1 = HL5507F: tolerance: 21.60964.207
LVDS1 = 50524-0300N-001: tolerance: 020.K0005.0030
MEMCD1 = 156-5101902601: tolerance: 062.10002.0161
NGFF1 = 2199230-7: tolerance: 62.10043.K51
PC50 PC52 = C805H58: tolerance: 78.10620.21LDL
PC2127 PC4304 PC5237 = C402H22: tolerance: 78.47124.2FLDL
PC4408 = C805H58: tolerance: 078.10522.021D
PC4426 = C603H36: tolerance: 78.10522.5BL
PC4603 PC4624 PC5419 = C402H22: tolerance: 78.33224.2FLDL
PC4610 PC4613 PC4621 PC5415 = C402H22: tolerance: 78.33124.2FLDL
PC4615 PC4617 PC5425 = C402H22: tolerance: 78.68124.2FLDL
PC4623 PC4628 PC5426 = C402H22: tolerance: 78.47321.2FLDL
PC4701 PC4702 PC4705 PC4707 PC4708 PC4711 PC4801 PC4808 PC4902 PC4904 PC5020-PC5022 PC5209 PC5214 PC5401 PC5402 PC5404 = C1206H71: tolerance: 78.10622.22LDL
PC4805 PC4917 PC4918 PC5013 = C402H22: tolerance: 78.18034.1FLDL
PC4911 PC4913 PC5203 = C402H22: tolerance: 78.22034.1FLDL
PC4915 PC4916 PC5017 PC5202 = C603H36: tolerance: 78.15224.2BLDL
PC5014 = C603H36: tolerance: 78.33322.2BLDL
PC5239 = C402H22: tolerance: 78.22124.2FLDL
PC5421 = C603H36: tolerance: 78.22521.5BLDL
PC5422 = C402H22: tolerance: 78.10423.2FLDL
PD4401 = D1608-035030AKH28: tolerance: 83.1R003.N8F
PD4405 = SOD323AKH42: tolerance: 83.04148.D1H
PG4801 PG4901-PG4908 PG5001 PG5211 PG5212 PG9001 = GAP-CLOSE-PWR-3: tolerance: ZZ.CLOSE.001
PG5205 PG5210 = GAP-CLOSE-PWR: tolerance: ZZ.CON2d.XXX
PL4301-PL4303 = L402H24: tolerance: 69.80007.021
PL4701 PL4702 PL5401 = L115100-2H158: tolerance: 68.R3610.10M
PL4802 = L686647H119: tolerance: 68.1R51A.10F
PL4903 = L686647-127318H119: tolerance: 68.3R31A.10V
PL4904 PL5202 = L686647H119: tolerance: 68.2R21B.10J
PL5001 = L686647H119: tolerance: 68.R681A.10A
PL5003 = L7066-1830-UH119: tolerance: 68.5R610.10X
PQ4204 = SOT323CBE2D2H44: tolerance: 84.00124.H1K
PQ4205 = SOT323CBE2D2H44: tolerance: 84.00124.K1K
PQ4206 PQ4408 Q1229 = SOT23DGS2D4H44: tolerance: 84.2N702.J31
PQ4406 PQ5006 Q37 Q6701 Q9646 = SOT-363H44: tolerance: 84.2N702.A3F
PQ4409 = SOT23CBE2D4H44: tolerance: 84.T3906.A11
PQ5003 PQ5004 Q1 Q3 Q5 Q47 Q51 Q56 Q64 Q68 Q103-Q105 Q107 Q1212 Q1249 Q9648 Q9650 = SOT23DGS2D4H48: tolerance: 84.2N702.E31
PQ5005 = SOT-363H44: tolerance: 84.00512.03F
PR24 PR4604 PR4606 PR4633 PR4642 R15 R22 R23 R35 R43 R51 R53 R56 R59 R60 R74 R99 R174 R205 R207 R222 R310 R372-R375 R383 R385 R399 R400 R502 R507 R515 R528 R529 R536 R568 R576 R638 R651 R666 R674 R707 R709 R723 R1199 R1203 R1209 R1611-R1613 R1647 R1653 R1654 R1668 R1697 R1698 R1709 R1711-R1714 R1718 R1719 R1739-R1741 R1744-R1748 R1762 R1842 R1857 R1858 R1901-R1904 R1912 R1981 R1984 R1985 R2017 R2053 R2054 R2080 R79633 R79634 R79639 R79640 R79686 R79708 R80225 = 0R0402-PAD-1: tolerance: ZZ.00PAD.M11
PR57 PR62 PR4450 PR4603 PR4608 PR4615 PR4624 PR4632 PR4917 PR4922 PR5005 PR5206 PR5209 PR5223 PR5282 PR5286 PR5292 PR5295 PR5408 PR5419 PR5429 PR5463 R82 R266 R357 R397 R404 R644 R645 R650 R655 R658 R702 R1760 R1808 R1809 R1823 R1824 R1830 R1832 R1834 R1835 R1841 R79621 R79625 R79705 R79706 R79723 R80216 R90040 R90041 = R402H16: tolerance: 64.10025.6DL
PR83 PR4612 PR4618 PR4685 PR5283 R5 R220 R284 R570 R571 R584 R585 R1686 R1735 = R402H14: tolerance: 64.10R05.6DL
PR190 PR4805 PR5431 R12 R41 R42 R124 R134 R137 R138 R152 R154 R159 R160 R163 R165 R175 R184 R213 R221 R281 R289 R294 R307 R308 R313 R316 R317 R334 R341 R350 R351 R364 R381 R382 R481-R483 R514 R517 R523 R524 R530 R531 R533 R582 R636 R637 R668 R675 R680 R682 R683 R717 R764 R774 R1178 R1183 R1185 R1186 R1188 R1194 R1634 R1635 R1659-R1663 R1670 R1672 R1674 R1679 R1683-R1685 R1687 R1688 R1700-R1703 R1705 R1707 R1716 R1724 R1725 R1728 R1731 R1733 R1734 R1736-R1738 R1749 R1753 R1754 R1757 R1759 R1783 R1785 R1819 R1825 R1826 R1829 R1840 R1845 R1849 R1868 R1870 R1872 R1875-R1877 R1926 R1932 R1933 R1935 R1986-R1988 R2010 R2012-R2014 R2055 R2056 R2061 R2062 R2064 R2077 R2091 R6702 R79635 R79637 R79638 R79650-R79654 R79659 R79670-R79673 R79676-R79681 R79687-R79690 R79694 R79714 R80212 R80217 R80218 R80221 R80222 R80230 R80233 R90012-R90021 R90032 R90047 R90048 R90051-R90056 R90068 R90073-R90075 = R402H16: tolerance: 63.10334.1DL
PR4210 R93 R143 R178 R225 R287 R297 R312 R314 R366 R369 R370 R377 R380 R384 R406 R433 R510 R542 R545 R627 R635 R679 R777 R1179 R1584 R1586 R1604-R1610 R1614-R1616 R1618 R1619 R1628 R1630 R1632 R1650 R1664-R1666 R1704 R1720 R1729 R1730 R1732 R1837 R1863 R1864 R1998 R2000 R2002 = R402H16: tolerance: 63.10234.1DL
PR4214 = R1206H28: tolerance: 63.33232.11L
PR4412 R208 R210 R1776 = R402H16: tolerance: 64.47025.6DL
PR4413 R319 R79628 R79720 R79722 R90031 = R402H16: tolerance: 64.10035.6DL
PR4425 PR4426 PR8519 PR8520 = R402H16: tolerance: 63.33234.1DL
PR4427 PR4431 PR4901 PR5273 PR5275 PR5278 PR5281 PR5289 PR5297 R1 R26 R30 R33 R118 R119 R132 R144 R179 R181 R353 R360 R361 R501 R504 R512 R513 R657 R732 R733 R1074 R1079 R1780 R1781 R1852 R1874 R2018 R4702 R4706 R6703-R6705 R79668 R90046 = R402H16: tolerance: 63.10434.1DL
PR4433 R19 R172 R722 R1779 = R402H16: tolerance: 63.10534.1DL
PR4451 = R402H16: tolerance: 64.68035.6DL
PR4455 PR4458 PR4462 PR4631 PR5247-PR5250 PR5420 PR5422 PR5464 PR5466 PR8521 R14 R31 R77 R81 R110 R125 R131 R206 R379 R413 R503 R618 R715 R716 R729 R1154 R1155 R1180 R1184 R1585 R1620-R1622 R1629 R1631 R1710 R1717 R1761 R1763 R1764 R1774 R1810 R1861 R1878 R1925 R1930 R1931 R1953 R1954 R1980 R1993-R1995 R1999 R2001 R2019 R2021 R2023 R2026 R2067 R2078 R2079 R4230 R6706 R79618 R79647-R79649 R79657 R79658 R79669 R79674 R79691 R79697-R79704 R79709-R79713 R79724 R79725 R80206-R80211 R80213 R80219 R80220 R80223 R80224 R80226 R80227 R80231 R80232 R90004 R90005 R90064 R90065 = R402H16: tolerance: 63.R0034.1DL
PR4601 PR4616 PR4621 PR4636 PR4638 PR5413 PR5417 PR5424 R61 R78 R115 R120 R122 R557 R559 R586 R742 R1163 R1588 R1633 R1644 R1649 R1657 R1721 R1989 R2028 R2057-R2060 R2065 R2066 R79661 R90066 = R402H16: tolerance: 64.10015.6DL
PR4602 PR5418 = R402H16: tolerance: 64.2R005.6DL
PR4605 PR4629 PR5421 = R402H16: tolerance: 64.61925.6DL
PR4609 PR4614 PR4626 PR5411 = R402H16: tolerance: 64.27425.6DL
PR4610 = R402H16: tolerance: 64.54925.6DL
PR4611 PR4628 PR4643 PR5410 PR5416 = R402H14: tolerance: 63.10134.1DL
PR4613 PR4630 = NTC-402H22-U: tolerance: 69.60037.031
PR4619 PR4640 PR4802 PR5425 = R402H16: tolerance: 64.75025.6DL
PR4620 PR5426 = R402H16: tolerance: 64.16535.6DL
PR4622 PR4634 PR5407 = R402H16: tolerance: 64.49R95.6DL
PR4623 PR4645 PR5415 R76 = R402H16: tolerance: 64.82015.6DL
PR4625 = R402H16: tolerance: 64.41225.6DL
PR4627 = R402H16: tolerance: 64.28725.6DL
PR4635 PR5412 = R402H16: tolerance: 64.24025.6DL
PR4637 PR4639 PR5414 = NTC-402H22-U: tolerance: 69.60011.081
PR4641 PR5009 = R402H16: tolerance: 64.48725.6DL
PR4644 R79623 R79627 = R402H16: tolerance: 64.30035.6DL
PR4701 PR4703 PR4812 PR5006 PR5404 PR5475 = R603H22: tolerance: 64.2R205.55L
PR4702 PR4704 PR5204 PR5401 = R1206H28: tolerance: 63.2R232.11L
PR4803 R1648 = R402H16: tolerance: 64.11825.6DL
PR4806 PR4902 PR4903 PR4911 PR4912 PR5034 PR5294 = R805H24: tolerance: 63.2R231.16L
PR4807 R20 R171 R1777 R1778 R90050 = R402H16: tolerance: 64.47035.6DL
PR4816 PR5268 = R402H16: tolerance: 64.33025.6DL
PR4914 = R402H16: tolerance: 64.66515.6DL
PR4918 PR5469 = R402H16: tolerance: 64.56225.6DL
PR4919 = R402H16: tolerance: 64.68025.6DL
PR4920 PR5468 = R402H16: tolerance: 64.11035.6DL
PR4921 R718 R762 R1658 R1690 R1691 R1727 R1817 R1853 R80215 = R402H16: tolerance: 64.15025.6DL
PR4924 = R402H16: tolerance: 64.24935.6DL
PR4925 = R402H16: tolerance: 64.19135.6DL
PR5002 = R402H16: tolerance: 64.5R105.6DL
PR5003 = R402H16: tolerance: 64.10525.6DL
PR5004 PR5291 PR5296 R276 = 0R0603-PAD: tolerance: ZZ.R0603.ZZZ
PR5007 = R402H16: tolerance: 64.62035.6DL
PR5023 = R402H16: tolerance: 64.40225.6DL
PR5201 R268 R1813 = R402H16: tolerance: 64.20025.6DL
PR5205 = R603H22: tolerance: 63.2R233.15L
PR5269 PR5276 = R3720H40: tolerance: 64.R0105.7FL
PR5270 = R402H16: tolerance: 64.30935.6DL
PR5272 = R402H16: tolerance: 64.49925.6DL
PR5274 PR5288 R744 = 0R0402-PAD: tolerance: ZZ.R0402.ZZZ
PR5277 = R402H16: tolerance: 64.7R505.6DL
PR5279 = R402H16: tolerance: 64.1R505.6DL
PR5284 = R805H24: tolerance: 64.20R05.16L
PR5285 = R402H16: tolerance: 63.47434.1DL
PR5287 = R402H16: tolerance: 63.33534.1DL
PR5293 = R402H16: tolerance: 64.88715.6DL
PR5298 = R402H16: tolerance: 64.12035.6DL
PR5402 = R402H16: tolerance: 64.34025.6DL
PR5409 = R402H16: tolerance: 64.39025.6DL
PR5423 = NTC-402H24-U: tolerance: 69.60028.041
PR5428 = R402H16: tolerance: 64.36025.6DL
PR5467 = R402H16: tolerance: 64.10235.6DL
PR5470 = R402H16: tolerance: 64.10735.6DL
PR5472 = R402H16: tolerance: 64.49915.6DL
PR5473 R689 = R402H16: tolerance: 64.64915.6DL
PT4701 PT4712 PT4901 PT5405 = SE361414H241: tolerance: 79.47612.3GL
PT4702-PT4704 PT4708 PT4709 PT4801 PT5401-PT5403 = ECAP-100D6D3H375: tolerance: 09.8271V.08L
PT4902 PT4903 = SE331721H237: tolerance: 79.22710.E0L
PT5007 = ECAP-100D6D3H355: tolerance: 09.8271N.A4L
PU4 = SOT23-2D8-312H58: tolerance: 74.02138.03B
PU5 = SOIC8-G3530H63: tolerance: 74.05337.031
PU4403 PU4405 PU4902-PU4905 = PPAK-8P-3232H36: tolerance: 84.07410.A37
PU4601 PU5407 = LFCSP52J6-G4D8H40: tolerance: 074.81128.0073
PU4702 PU4802 PU5006 PU5207 PU5401 = PPAK-8P-5262H40: tolerance: 84.06520.037
PU4703-PU4706 PU4801 PU5007 PU5402 PU5403 = PPAK-8P-5262H40: tolerance: 084.06510.0037
PU4803 = DFN10G3-G265175H32: tolerance: 74.08237.B73
PU4901 = QFN20-G1D75H32: tolerance: 74.08243.073
PU5001 = QFN20-G1D75H32: tolerance: 74.08207.C73
PU5201 = QFN16J3H24: tolerance: 074.06220.0043
PU5204 PU5205 U110 = SOIC8H69: tolerance: 84.04407.G37
PU5206 = SOIC8-G3530H63: tolerance: 74.05930.B3D
PWRCN1 = 51530-01041-W01: tolerance: 20.K0642.010
Q4 Q7 Q18 Q65 Q95 Q1217 Q1226 Q4701 = SOT-363H44: tolerance: 75.27002.F7C
Q10 Q22 Q31 Q38 Q45 Q52 Q100-Q102 Q128 Q1207 Q1208 Q1213 Q1214 Q1241 = SOT23CBE2D4H44: tolerance: 84.T3904.C11
Q12 Q13 Q36 Q63 = SOT-363H44: tolerance: 84.M3904.B1F
Q14 = SOT23DGS2D4H35: tolerance: 84.3K329.031
Q24 Q46 Q57 = SOT23-2D4-312H46: tolerance: 75.05125.07D
Q28 Q1209 Q1240 Q1243-Q1245 Q1247 Q1248 Q90001 Q90002 = SOT23DGS2D4H44: tolerance: 84.27002.W31
Q43 U2 = SOIC8H69: tolerance: 84.04468.A37
Q44 Q1210 Q1211 Q9647 Q9649 = SOT23DGS2D8H50: tolerance: 84.03413.B31
Q50 = SOT-23-10H44: tolerance: 84.03904.L06
Q78 Q79 Q1227 Q1246 = SOT23DGS2D4H44: tolerance: 84.27002.Z31
Q1250 = SOIC8H69: tolerance: 084.04286.0037
Q6703 Q6704 = DFN6F2030-G1619H26: tolerance: 075.02016.007C
R8 = R603H22: tolerance: 63.33133.15L
R10 R378 R775 R80228 = R402H16: tolerance: 63.82234.1DL
R13 R776 R80229 = R402H16: tolerance: 64.39225.6DL
R24 R216 R305 R1595 R1784 R2022 R2025 R2029-R2032 R6701 R79655 R79707 R90001 R90002 R90008-R90011 R90069-R90072 = R603H22: tolerance: 63.00000.00L
R27 R79622 = R1206H26: tolerance: 64.R3305.41L
R32 R46 R47 R54 R57 R58 R69 R80 R133 R135 R139 R508 R526 R527 R535 R634 R731 R755 R1699 R1752 R1758 R1782 R1831 R1844 R1860 R80201 R80202 R90039 = R402H16: tolerance: 63.47234.1DL
R37 R79631 = 0R1206-PAD-1: tolerance: ZZ.R1206.ZZ1
R39 R123 R1645 R1646 R1934 R90033-R90038 R90042-R90045 = R402H16: tolerance: 63.22034.1DL
R45 R68 R111 R371 R484 = R402H14: tolerance: 64.10005.6DL
R65 R1708 R79643-R79646 R79656 = R805H24: tolerance: 63.R0031.16L
R71 R162 R223 R261 R262 R272 R1669 R1673 R1675 R1676 R1843 R2083 R2084 = R402H16: tolerance: 63.22234.1DL
R73 R368 R639 R643 R656 = R402H16: tolerance: 63.20334.1DL
R107 = R402H16: tolerance: 64.15005.6DL
R113 R322 R407 R90057 = R603H22: tolerance: 64.10045.55L
R121 R1696 = R402H16: tolerance: 64.39R25.6DL
R209 R306 R309 R352 R743 R758 R1678 R1743 R1755 R1756 R1851 R79682-R79685 = R402H16: tolerance: 63.33034.1DL
R212 = R402H16: tolerance: 64.68R05.6DL
R215 R300 R301 R344-R346 R356 R359 R367 R1182 R1193 R1601 = 0R0603-PAD-1-U: tolerance: ZZ.00PAD.M21
R267 = R402H16: tolerance: 64.51015.6DL
R347 = R402H16: tolerance: 64.39015.6DL
R355 R365 = R603H22: tolerance: 64.10525.55L
